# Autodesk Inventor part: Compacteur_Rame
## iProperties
Created: 2008-12
Part Number: Compacteur_Rame
Document SubType Name: Modeling
Designer: claivier
Author: claivier
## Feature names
1. Extrusion1
2. Extrusion4
3. Congé1 [Fillet]
4. Extrusion5
5. Chanfrein1 [Chamfer]
6. Perçage1 [Hole]
7. Perçage2 [Hole]
8. Extrusion6
9. Miroir1 [Mirror]
10. Miroir2 [Mirror]
11. Extrusion7
12. Congé2 [Fillet]
13. Congé3 [Fillet]
